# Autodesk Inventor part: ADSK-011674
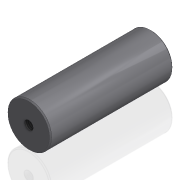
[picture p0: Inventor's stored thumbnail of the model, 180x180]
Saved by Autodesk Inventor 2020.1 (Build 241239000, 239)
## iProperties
Created: 2000-02
Part Number: ADSK-011674
Description: SHFTTA,RC,AX,035,12,XD,MNT,BUMPER
Document SubType Name: Modeling
Designer: sgadau
Material: Acier doux
Density: 7.86 g/cm^3
Appearance: Metal-Steel(Polish)
Mass: 540.266 g
Surface Area: 112.952 cm^2
Volume: 68.7361 cm^3
Control State: 0
Master: False
Checked Out: False
Shininess: 60.0
Length Units: 11269
Angle Units: 11279
Time Units: 11290
Mass Units: 11283
Length Display Precision: 3
Angle Display Precision: 2
Compacted: True
Cutlength: 3.75
Material Desc: ROUND,CD 1018,1.2500 DIA
Material_Number: A084566
Dimensions: 31,7x31,8x88,9 mm
Mass: 0,54 kg
Density: 7.86
Volumn: 60.32985923004582
Area: 91.84073058642146
PropertySet Name: Model Information
Title: 500625
Author: sgadau
Revision Number: -
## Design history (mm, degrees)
node "Extrusion1" dims "d1" = 88.9, "d2" = 0
node "Hole1" dims "d3" = 6.647, "d4" = 9.525, "d5" = 6.35, "d6" = 60 deg, "d7" = 22.2, "d8" = 118 deg, "d18" = 16
node "Hole2" dims "d9" = 6.647, "d10" = 9.525, "d11" = 6.35, "d12" = 60 deg, "d13" = 22.2, "d14" = 118 deg, "d19" = 16
node "Chamfer1" dims "d15" = 0.79375, "d16" = 0.79375, "d17" = 45 deg
node "Solide1"
node "Corps solides"
node "Corps surfaciques"
sketch "Sketch1"
  geometry: C1 r 15.875 at (-48.636, 110.022)
  constraints: 1 centre point, 1 other
  dimensions: "d0" = 31.75 diameter of C1
sketch "Sketch2"
  geometry: C1 r 15.875 at (0, 0) reference; 1 further point
  constraints: 1 coincident
sketch "Sketch3"
  geometry: C1 r 15.875 at (0, 0) reference; 1 further point
  constraints: 1 coincident
